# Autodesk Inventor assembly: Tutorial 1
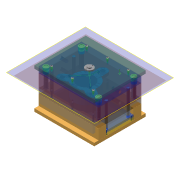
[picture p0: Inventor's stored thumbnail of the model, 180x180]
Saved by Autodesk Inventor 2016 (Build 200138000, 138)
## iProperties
Created: 2015-04
Part Number: Tutorial 1
Document SubType Name: Assembly
Designer: Sandeep
Author: Sandeep
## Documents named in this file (7)
- C:\Autodesk Inventor 2016\c19\Tutorial 1.iam
- C:\Autodesk Inventor 2016\c19\Tutorial 1_c19_Inv_tut01_LY.iam
- C:\Autodesk Inventor 2016\c19\Tutorial 1_RG.ipt
- C:\Autodesk Inventor 2016\c19\MB\FUTABA_SA-S 1\Tutorial 1_MB.iam
- C:\Autodesk Inventor 2016\c19\Sprue Bushing\DME_AGN\Tutorial 1_AGN 76-3.5-0.ipt
- C:\Autodesk Inventor 2016\c19\Locating Ring\RABOURDIN_646 - Type B\Tutorial 1_646-90-25-12.5.ipt
- C:\Autodesk Inventor 2016\c19\Tutorial 1_CH.ipt
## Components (6 placed, 6 different names)
1. Tutorial 1_c19_Inv_tut01_LY:1 [sub-assembly] — Flush:1, Flush:2, Flush:3, Flush:4, Flush:10
2. Tutorial 1_RG:1 — Flush:5, Flush:6, Flush:7, Flush:9, Mate:3
3. Tutorial 1_MB:1 [sub-assembly] — Flush:10, Mate:1, Angle:1, Mate:2, Mate:4
4. Tutorial 1_AGN 76-3.5-0:1 — Mate:2, Mate:3, Mate:5
5. Tutorial 1_646-90-25-12.5:1 — Mate:4, Mate:5
6. Tutorial 1_CH:1
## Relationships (15: Flush 9, Mate 5, Angle 1)
- Flush:1: Tutorial 1_c19_Inv_tut01_LY:1
- Flush:2: Tutorial 1_c19_Inv_tut01_LY:1
- Flush:3: Tutorial 1_c19_Inv_tut01_LY:1
- Flush:4: Tutorial 1_c19_Inv_tut01_LY:1
- Flush:5: Tutorial 1_RG:1
- Flush:6: Tutorial 1_RG:1
- Flush:7: Tutorial 1_RG:1
- Flush:9: Tutorial 1_RG:1
- Flush:10: Tutorial 1_c19_Inv_tut01_LY:1 ↔ Tutorial 1_MB:1
- Mate:1: Tutorial 1_MB:1
- Angle:1: Tutorial 1_MB:1
- Mate:2: Tutorial 1_MB:1 ↔ Tutorial 1_AGN 76-3.5-0:1
- Mate:3: Tutorial 1_RG:1 ↔ Tutorial 1_AGN 76-3.5-0:1
- Mate:4: Tutorial 1_MB:1 ↔ Tutorial 1_646-90-25-12.5:1
- Mate:5: Tutorial 1_AGN 76-3.5-0:1 ↔ Tutorial 1_646-90-25-12.5:1
